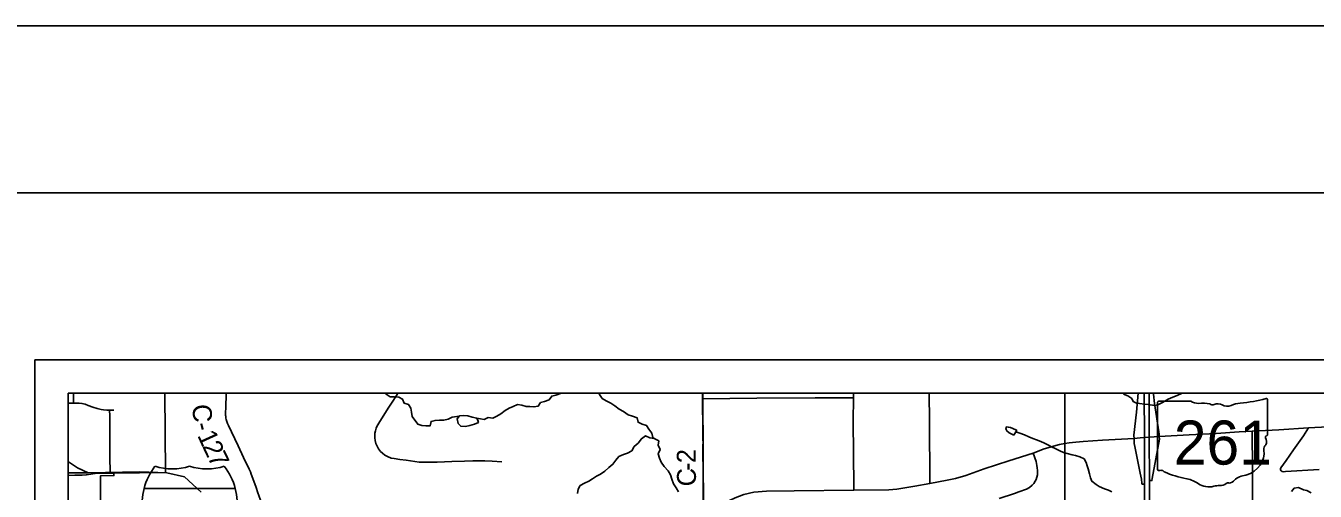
# Model space of a CAD drawing. Extents: x 0 to 34, y -5 to 22.
# Drawn here: x 1.973 to 5.836, y 20.607 to 22 of the extents above; entities that cross this region are included whole.
import ezdxf

# ---------------------------------------------------------------- set-up
doc = ezdxf.new("R2010")
doc.units = 0
for name, color, linetype in [('GM_X_City_Street', 7, 'Continuous'), ('GM_X_County_Road', 7, 'Continuous'), ('GM_X_County_Road_Text', 7, 'Continuous'), ('GM_X_Interchange_Ramps', 7, 'Continuous'), ('GM_X_Interstate_Shield', 7, 'Continuous'), ('GM_X_Minor_Lake', 7, 'Continuous'), ('GM_X_Minor_River', 7, 'Continuous'), ('GM_X_Rail_Line', 7, 'Continuous'), ('GM_X_State_Location', 7, 'Continuous'), ('GM_X_State_Route', 7, 'Continuous'), ('GM_X_State_Shield', 7, 'Continuous'), ('GM_X_Township_Road', 7, 'Continuous'), ('GM_X_US_Route', 7, 'Continuous'), ('SC_Scratch2', 7, 'Continuous'), ('SH_Border', 7, 'Continuous'), ('SH_Cut_Line', 7, 'Continuous'), ('SH_Data', 7, 'Continuous')]:
    doc.layers.add(name, color=color, linetype=linetype)

msp = doc.modelspace()

# ---------------------------------------------------------------- linework, layer by layer
at = {"layer": 'GM_X_City_Street'}
msp.add_line((2.1157, 20.8701), (2.1155, 20.9), dxfattribs=at)
for points in [[(4.453, 20.6099), (4.4534, 20.6213), (4.4515, 20.816), (4.452, 20.8865), (4.4521, 20.9)], [(4.6811, 20.6298), (4.6805, 20.6348), (4.6796, 20.815), (4.679, 20.9)], [(2.1, 20.8701), (2.1046, 20.8701), (2.1157, 20.8701), (2.1321, 20.8698), (2.1409, 20.8692), (2.1506, 20.8669), (2.1594, 20.8636), (2.1734, 20.8586), (2.1869, 20.8538), (2.1986, 20.8508), (2.2057, 20.8499), (2.215, 20.8493), (2.2237, 20.8493), (2.2364, 20.8494)], [(4.0006, 20.8834), (4.0006, 20.8834), (4.1631, 20.8848), (4.3376, 20.8863), (4.452, 20.8865)], [(2.225, 20.6607), (2.2242, 20.712), (2.2239, 20.8323), (2.2237, 20.8493)], [(5.6498, 20.2289), (5.6484, 20.2315), (5.6479, 20.2348), (5.6479, 20.2379), (5.6477, 20.244), (5.6477, 20.3025), (5.6472, 20.4479), (5.6465, 20.4906), (5.6472, 20.6206), (5.6477, 20.672), (5.6468, 20.7866)], [(5.7315, 20.6703), (5.7318, 20.6736), (5.7329, 20.677), (5.7481, 20.6988), (5.7701, 20.7309), (5.8003, 20.7728), (5.8158, 20.7961)], [(4.8885, 20.5848), (4.9344, 20.6), (4.9476, 20.6044), (4.9702, 20.6124), (4.9796, 20.618), (4.9877, 20.6248), (4.9924, 20.6298), (4.9967, 20.6362), (4.9993, 20.6421), (5.0014, 20.6488), (5.0033, 20.6559), (5.0038, 20.6625), (5.0036, 20.6684), (5.0029, 20.6767), (5.0019, 20.6831), (4.9993, 20.6954), (4.9904, 20.7209)], [(5.7315, 20.6703), (5.7334, 20.6677), (5.7363, 20.6658), (5.7403, 20.6649), (5.7465, 20.6651), (5.8478, 20.6717)], [(2.1, 20.6541), (2.1191, 20.6542), (2.1414, 20.6545), (2.1537, 20.6552), (2.1676, 20.6577), (2.1805, 20.6599), (2.1911, 20.661), (2.2154, 20.6608), (2.225, 20.6607), (2.2377, 20.6607)]]:
    msp.add_lwpolyline(points, dxfattribs=at)
at = {"layer": 'GM_X_County_Road'}
msp.add_line((4.0006, 20.8834), (4.0006, 20.9), dxfattribs=at)
for points in [[(2.6753, 20.58), (2.6707, 20.5937), (2.6679, 20.602), (2.6628, 20.6175), (2.6531, 20.6444), (2.6481, 20.6577), (2.6455, 20.6642), (2.6417, 20.6727), (2.6252, 20.7078), (2.6086, 20.7425), (2.5885, 20.7848), (2.5797, 20.8037), (2.5773, 20.8091), (2.5748, 20.8155), (2.5733, 20.8212), (2.5723, 20.8251), (2.5717, 20.8285), (2.5714, 20.8313), (2.5713, 20.8332), (2.571, 20.8398), (2.5717, 20.8586), (2.5731, 20.8972), (2.5732, 20.9)], [(5.0725, 17.9168), (5.0746, 18.0892), (5.0751, 18.1236), (5.0746, 18.1584), (5.076, 18.2214), (5.0763, 18.2257), (5.0765, 18.3047), (5.0777, 18.3384), (5.0777, 18.5427), (5.0793, 18.7403), (5.0805, 18.9401), (5.0808, 19.1246), (5.081, 19.4273), (5.0819, 19.5963), (5.0824, 19.6307), (5.0824, 19.8505), (5.0836, 20.0558), (5.0846, 20.0998), (5.0842, 20.1129), (5.0864, 20.3819), (5.0857, 20.5652), (5.085, 20.7499), (5.0856, 20.9)], [(4.0018, 20.6547), (4.0018, 20.6557), (4.0018, 20.6777), (4.0013, 20.7116), (4.0015, 20.7853), (4.0007, 20.8252), (4.0008, 20.8517), (4.0006, 20.8768), (4.0006, 20.8834)], [(4.0032, 20.5386), (4.0025, 20.5563), (4.002, 20.6006), (4.0017, 20.6257), (4.0018, 20.6547)]]:
    msp.add_lwpolyline(points, dxfattribs=at)
at = {"layer": 'GM_X_Interchange_Ramps'}
for points in [[(5.3055, 20.9), (5.2997, 20.8428), (5.2924, 20.7741), (5.2924, 20.7734), (5.2927, 20.7648)], [(5.3681, 20.7701), (5.3677, 20.7779), (5.3674, 20.7843), (5.3544, 20.8694), (5.3506, 20.8967), (5.3501, 20.9)], [(5.2927, 20.7648), (5.293, 20.7598), (5.2932, 20.756), (5.2935, 20.7494), (5.2952, 20.7404), (5.3112, 20.6609), (5.3149, 20.6428), (5.3165, 20.6302), (5.3169, 20.6281), (5.3242, 20.6281)], [(5.3386, 20.6384), (5.3463, 20.6384), (5.3473, 20.6449), (5.3686, 20.762), (5.3681, 20.7701)]]:
    msp.add_lwpolyline(points, dxfattribs=at)
at = {"layer": 'GM_X_Interstate_Shield'}
for p, q in [((2.3269, 20.6147), (2.6001, 20.6147)), ((2.6001, 20.6147), (2.3269, 20.6147)), ((2.6001, 20.6147), (2.3269, 20.6147))]:
    msp.add_line(p, q, dxfattribs=at)
for centre, start, end in [((2.499, 20.5712), 141.669, 165.8066), ((2.4116, 20.8511), 253.0091, 286.9909), ((2.5154, 20.8511), 253.0091, 286.9909), ((2.428, 20.5712), 14.1934, 38.331), ((2.499, 20.5712), 165.8066, 258.463), ((2.428, 20.5712), 281.537, 14.1934)]:
    msp.add_arc(centre, 0.1776, start, end, dxfattribs=at)
at = {"layer": 'GM_X_Minor_Lake'}
for points in [[(3.3273, 20.8182), (3.3238, 20.8249), (3.3101, 20.8278), (3.2971, 20.8319), (3.2849, 20.8333), (3.272, 20.8327), (3.2653, 20.8228), (3.2684, 20.8091)], [(3.3271, 20.8187), (3.3238, 20.8249), (3.3101, 20.8278), (3.2971, 20.8319), (3.2849, 20.8333), (3.272, 20.8327), (3.2653, 20.8228), (3.2684, 20.8091)], [(3.2684, 20.8091), (3.2758, 20.8012), (3.2895, 20.8002), (3.3031, 20.803), (3.3171, 20.807), (3.3285, 20.8121), (3.3272, 20.8188)], [(3.2684, 20.8091), (3.2758, 20.8012), (3.2895, 20.8002), (3.3031, 20.803), (3.3171, 20.807), (3.3285, 20.8121), (3.3273, 20.8182)], [(4.9413, 20.7894), (4.9341, 20.7928), (4.9292, 20.7939), (4.9223, 20.7969), (4.9159, 20.7988), (4.9106, 20.7991), (4.9083, 20.7938), (4.9114, 20.7869), (4.919, 20.7817), (4.9323, 20.7745)], [(4.9323, 20.7745), (4.9413, 20.7894)]]:
    msp.add_lwpolyline(points, dxfattribs=at)
at = {"layer": 'GM_X_Minor_River'}
for points in [[(3.2707, 20.8313), (3.2504, 20.8287), (3.2383, 20.8221), (3.2254, 20.8193), (3.2117, 20.8195), (3.1988, 20.8186), (3.187, 20.8154), (3.1841, 20.8024), (3.1712, 20.8019), (3.159, 20.8037), (3.1468, 20.807), (3.1306, 20.8304), (3.1282, 20.8433), (3.1258, 20.8554), (3.1192, 20.8664), (3.1062, 20.87), (3.1015, 20.8822), (3.09, 20.8885), (3.0775, 20.8895), (3.0638, 20.889), (3.0527, 20.8972), (3.0505, 20.9)], [(3.5761, 20.9), (3.575, 20.8989), (3.561, 20.8946), (3.5481, 20.8914), (3.5402, 20.8799), (3.527, 20.8756), (3.5148, 20.872), (3.5077, 20.8613), (3.4948, 20.8588), (3.4823, 20.8606), (3.472, 20.8605), (3.4587, 20.8645), (3.4453, 20.8659), (3.4332, 20.8604), (3.4207, 20.855), (3.409, 20.8487), (3.3958, 20.8383), (3.3834, 20.8313), (3.3713, 20.8251), (3.358, 20.8269), (3.3455, 20.8214), (3.324, 20.8248)], [(3.855, 20.7645), (3.8548, 20.7647), (3.8513, 20.767), (3.8477, 20.7807), (3.8396, 20.792), (3.8322, 20.8033), (3.8193, 20.8074), (3.807, 20.8133), (3.8042, 20.8262), (3.7905, 20.8314), (3.7768, 20.835), (3.763, 20.8448), (3.7503, 20.8526), (3.7369, 20.8624), (3.7251, 20.8698), (3.7117, 20.8773), (3.6994, 20.8844), (3.6913, 20.8961), (3.6889, 20.9)], [(5.4374, 20.9), (5.4215, 20.8933), (5.4086, 20.8883), (5.3946, 20.8821), (5.378, 20.8718), (5.364, 20.8652), (5.3538, 20.8636), (5.3352, 20.8658), (5.3238, 20.8673), (5.3094, 20.8691), (5.2999, 20.8706), (5.2904, 20.8747), (5.2858, 20.8842), (5.2744, 20.8917), (5.2615, 20.8969)], [(5.0709, 20.7271), (5.0561, 20.7342), (5.0458, 20.7395), (5.0363, 20.7447), (5.0242, 20.7507), (5.0135, 20.7552), (5.0006, 20.7609), (4.99, 20.7642), (4.9774, 20.7695), (4.9641, 20.7751), (4.9505, 20.7803), (4.9382, 20.7842)], [(3.9276, 20.605), (3.921, 20.6168), (3.9129, 20.6285), (3.9082, 20.6425), (3.9042, 20.6554), (3.8972, 20.6675), (3.8849, 20.6803), (3.8764, 20.6931), (3.8714, 20.7056), (3.867, 20.7189), (3.873, 20.7319), (3.8671, 20.7444), (3.8693, 20.7573), (3.8555, 20.7644), (3.8425, 20.7665), (3.8288, 20.7721), (3.8167, 20.7636), (3.8074, 20.7509), (3.7957, 20.7401), (3.7882, 20.7275), (3.775, 20.7201), (3.7629, 20.7165), (3.7493, 20.7103), (3.7399, 20.6995), (3.7313, 20.6873), (3.7196, 20.6776), (3.7072, 20.6668), (3.694, 20.6579), (3.6819, 20.6517), (3.6706, 20.6436), (3.6589, 20.637), (3.646, 20.6308), (3.6335, 20.6234), (3.6276, 20.6127), (3.6251, 20.6001)], [(5.2266, 20.6052), (5.2163, 20.6097), (5.2045, 20.6142), (5.1886, 20.6205), (5.1791, 20.6262), (5.1665, 20.6364), (5.1627, 20.6466), (5.1596, 20.6584), (5.1553, 20.6732), (5.1526, 20.6827), (5.1495, 20.6925), (5.1434, 20.7032), (5.1301, 20.7099), (5.1176, 20.7133), (5.107, 20.7155), (5.0929, 20.7196), (5.0815, 20.7226), (5.0709, 20.7271)], [(5.8232, 20.6022), (5.8107, 20.609), (5.8008, 20.6108), (5.7856, 20.6176), (5.7724, 20.6152), (5.7645, 20.6057)]]:
    msp.add_lwpolyline(points, dxfattribs=at)
at = {"layer": 'GM_X_Rail_Line'}
msp.add_line((2.1593, 20.6613), (2.1, 20.662), dxfattribs=at)
for points in [[(2.1, 20.6968), (2.1031, 20.6927), (2.1273, 20.6763), (2.1593, 20.6613)], [(2.4979, 20.6037), (2.4479, 20.6498), (2.395, 20.6615), (2.3147, 20.6645), (2.1593, 20.6613)]]:
    msp.add_lwpolyline(points, dxfattribs=at)
at = {"layer": 'GM_X_State_Route'}
for points in [[(5.3245, 20.4859), (5.3242, 20.6281), (5.3238, 20.7672), (5.3235, 20.9)], [(5.3386, 20.6384), (5.3379, 20.7683), (5.3379, 20.9)], [(5.4578, 20.775), (5.5385, 20.7794), (5.6081, 20.7844), (5.6468, 20.7866), (5.7269, 20.7908), (5.8158, 20.7961), (5.9309, 20.8026), (6.09, 20.8115), (6.2296, 20.8205), (6.3192, 20.8256), (6.4266, 20.8325), (6.5009, 20.8363), (6.5169, 20.8369), (6.6108, 20.8437)], [(4.2745, 20.608), (4.453, 20.6099), (4.5585, 20.6104), (4.5817, 20.6127), (4.6358, 20.6215), (4.6811, 20.6298), (4.7325, 20.6392), (4.7579, 20.645), (4.7888, 20.6541), (4.844, 20.6731), (4.9177, 20.6977), (4.9904, 20.7209), (5.0238, 20.7331), (5.0696, 20.7466), (5.085, 20.7499)], [(5.085, 20.7499), (5.0984, 20.7513), (5.1188, 20.7538), (5.1406, 20.7557), (5.1982, 20.7591)], [(5.1982, 20.7591), (5.2927, 20.7648), (5.3115, 20.7663)], [(5.3115, 20.7663), (5.3238, 20.7672), (5.3379, 20.7683), (5.3681, 20.7701), (5.4578, 20.775)], [(5.3161, 20.1844), (5.3211, 20.2209), (5.3232, 20.2363), (5.3297, 20.2827), (5.3344, 20.3316), (5.3371, 20.3668), (5.3389, 20.413), (5.3392, 20.4859), (5.3389, 20.6282), (5.3386, 20.6384)], [(4.0033, 20.5357), (4.0642, 20.5707), (4.0973, 20.5867), (4.1238, 20.5966), (4.1542, 20.6033), (4.1912, 20.6071), (4.2745, 20.608)]]:
    msp.add_lwpolyline(points, dxfattribs=at)
at = {"layer": 'GM_X_State_Shield'}
for p, q in [((5.3631, 20.8723), (5.3631, 20.6722)), ((5.4629, 20.8758), (5.3663, 20.8758)), ((5.6927, 20.7761), (5.6927, 20.8807)), ((5.6926, 20.7761), (5.6927, 20.7761))]:
    msp.add_line(p, q, dxfattribs=at)
for centre, major_axis, start_param, end_param in [((5.3669, 20.8728), (0.00382, 0), 1.712693, 3.28349), ((5.4858, 20.899), (0.037, 0), 4.042523, 4.731795), ((5.4981, 20.7634), (0.133, 0), 1.404758, 1.657858), ((5.5283, 20.8738), (0.0107, 0), 3.836095, 5.185415), ((5.544, 20.8507), (0.0222, 0), 0.950623, 2.079405), ((5.5727, 20.8824), (0.0267, 0), 4.081561, 5.145723), ((5.6199, 20.8147), (0.0703, 0), 1.699011, 2.107814), ((5.5753, 21.1486), (0.3495, 0), 4.814394, 5.042369), ((5.689, 20.8812), (0.00367, 0), 6.141152, 7.989035), ((5.7058, 20.7322), (0.0248, 0), 2.387724, 3.262537), ((5.6918, 20.7684), (0.00568, 0), 1.883978, 3.671073), ((5.6557, 20.7551), (0.0341, 0), 5.934695, 6.695948), ((5.6888, 20.7757), (0.00393, 0), 5.05454, 6.418171), ((5.5949, 20.7189), (0.0874, 0), 5.101752, 6.440018), ((5.3669, 20.6718), (0.00385, 0), 3.00124, 4.508301), ((5.3675, 20.6923), (0.0294, 0), 4.665946, 4.897461), ((5.3735, 20.6607), (0.0106, 0), 0.519207, 1.627899), ((5.5073, 20.8405), (0.2524, 0), 4.195997, 4.488961), ((5.4321, 20.5823), (0.079, 0), 0.823519, 1.323587), ((5.5175, 20.6597), (0.0501, 0), 4.026481, 4.996735), ((5.5501, 20.6447), (0.0267, 0), 4.691044, 5.507374), ((5.5743, 20.6253), (0.00752, 0), 1.147584, 2.315152), ((5.5711, 20.6528), (0.0282, 0), 4.937069, 5.64225), ((5.6317, 20.616), (0.0479, 0), 1.647645, 2.488434), ((5.5464, 20.5905), (0.0412, 0), 1.495662, 1.94098)]:
    msp.add_ellipse(centre, major_axis=major_axis, ratio=0.8, start_param=start_param, end_param=end_param, dxfattribs=at)
at = {"layer": 'GM_X_Township_Road'}
msp.add_lwpolyline([(2.3894, 20.9), (2.1, 20.9), (2.1, 20.4752), (2.1972, 20.4761), (2.1969, 20.6528), (2.2368, 20.6532), (2.2367, 20.6608), (2.3907, 20.6626)], close=True, dxfattribs=at)
for points in [[(2.9992, 20.9), (2.9993, 20.9), (3.0015, 20.8998), (3.0023, 20.9)], [(3.3988, 20.695), (3.3698, 20.697), (3.3476, 20.6977), (3.3271, 20.6975), (3.3114, 20.6972), (3.2873, 20.6964), (3.2488, 20.6951), (3.2051, 20.6938), (3.1778, 20.6932), (3.1615, 20.6933), (3.1509, 20.6937), (3.1122, 20.6993), (3.0929, 20.7016), (3.0762, 20.7041), (3.0669, 20.706), (3.0561, 20.7105), (3.0486, 20.7143), (3.0412, 20.7207), (3.0351, 20.7259), (3.0295, 20.7335), (3.0248, 20.7413), (3.0209, 20.7499), (3.0189, 20.7585), (3.0181, 20.7667), (3.0178, 20.7733), (3.0185, 20.7804), (3.02, 20.7877), (3.0224, 20.795), (3.0244, 20.8002), (3.0272, 20.8058), (3.0329, 20.8153), (3.0451, 20.8339), (3.0587, 20.8553), (3.0705, 20.8736), (3.0831, 20.8936), (3.0873, 20.9)]]:
    msp.add_lwpolyline(points, dxfattribs=at)
at = {"layer": 'GM_X_US_Route'}
for points in [[(4.0056, 17.7327), (4.0095, 18.3868), (4.0098, 19.1097), (4.005, 19.9814), (4.0049, 20.0266), (4.0047, 20.1034), (4.0052, 20.1906), (4.0053, 20.2144), (4.0055, 20.2299), (4.0039, 20.4099), (4.0031, 20.5369), (4.0016, 20.728), (4.0011, 20.7857), (4.0002, 20.8844), (4.0002, 20.9), (2.1, 20.9), (2.1, 16.5221)], [(8.9, 20.9), (4.0002, 20.9), (4.0002, 20.8844), (4.0011, 20.7857), (4.0016, 20.728), (4.0031, 20.5369), (4.0039, 20.4099), (4.0055, 20.2299), (4.0053, 20.2144), (4.0052, 20.1906), (4.0047, 20.1034), (4.0049, 20.0266), (4.005, 19.9814), (4.0098, 19.1097), (4.0095, 18.3868), (4.0056, 17.7327)]]:
    msp.add_lwpolyline(points, dxfattribs=at)
at = {"layer": 'SC_Scratch2'}
msp.add_lwpolyline([(8.9, 20.9), (4.0005, 20.9), (4.0011, 20.7857), (4.0016, 20.728), (4.0031, 20.5369), (4.0054, 20.2251), (4.0052, 20.1906), (4.005, 20.1517), (4.005, 19.9814), (4.0088, 19.1096), (4.0056, 17.7327)], dxfattribs=at)
at = {"layer": 'SH_Border'}
msp.add_lwpolyline([(1.5, 21.5), (33.5, 21.5), (33.5, 0.5), (1.5, 0.5)], close=True, dxfattribs=at)
at = {"layer": 'SH_Cut_Line'}
msp.add_lwpolyline([(0, 0), (34, 0), (34, 22), (0, 22)], close=True, dxfattribs=at)
for points in [[(4.0056, 17.7327), (4.0095, 18.3868), (4.0098, 19.1097), (4.005, 19.9814), (4.0049, 20.0266), (4.0047, 20.1034), (4.0052, 20.1906), (4.0053, 20.2144), (4.0055, 20.2299), (4.0039, 20.4099), (4.0031, 20.5369), (4.0016, 20.728), (4.0011, 20.7857), (4.0002, 20.8844), (4.0002, 20.9), (2.1, 20.9), (2.1, 16.5221)], [(8.9, 20.9), (4.0002, 20.9), (4.0002, 20.8844), (4.0011, 20.7857), (4.0016, 20.728), (4.0031, 20.5369), (4.0039, 20.4099), (4.0055, 20.2299), (4.0053, 20.2144), (4.0052, 20.1906), (4.0047, 20.1034), (4.0049, 20.0266), (4.005, 19.9814), (4.0098, 19.1097), (4.0095, 18.3868), (4.0056, 17.7327)]]:
    msp.add_lwpolyline(points, dxfattribs=at)
at = {"layer": 'SH_Data'}
for p, q in [((2, 21), (9, 21)), ((2, 21), (2, 14)), ((2.1, 20.9), (2.1, 14.1)), ((2.1, 20.9), (8.9, 20.9))]:
    msp.add_line(p, q, dxfattribs=at)

# ---------------------------------------------------------------- texts
at = {"layer": 'GM_X_County_Road_Text'}
for s, rotation, p in [('C', 272.7683, (2.4719, 20.8659)), ('1', 294.4562, (2.4855, 20.774)), ('-', 284.4337, (2.4761, 20.8068)), ('2', 295.3848, (2.5004, 20.7412)), ('7', 295.5864, (2.5155, 20.7094)), ('2', 90.4537, (3.9799, 20.6908)), ('C', 90.4325, (3.9805, 20.6213)), ('-', 90.4355, (3.9801, 20.6677))]:
    msp.add_text(s, height=0.0568, rotation=rotation, dxfattribs=at).set_placement(p)
at = {"layer": 'GM_X_State_Location'}
msp.add_text('261', height=0.000189, rotation=0, dxfattribs=at).set_placement((5.4573, 20.7452))
for s in ['s', 'r']:
    msp.add_text(s, height=0.000189, dxfattribs=at).set_placement((5.5242, 20.759))
at = {"layer": 'GM_X_State_Shield'}
msp.add_text('261', height=0.13184, dxfattribs=at).set_placement((5.4117, 20.6863))

doc.saveas('drawing.dxf')
